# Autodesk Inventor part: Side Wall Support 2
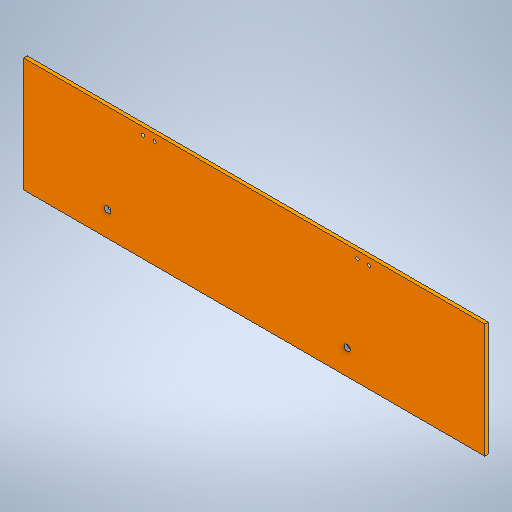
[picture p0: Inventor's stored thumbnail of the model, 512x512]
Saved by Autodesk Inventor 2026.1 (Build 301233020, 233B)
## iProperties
Created: 2026-11
Part Number: Side Wall Support 2
Material: Generic
Document SubType Name: Modeling
Designer: hp
Density: 1 g/cm^3
Appearance: Default
Author: hp
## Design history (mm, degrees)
sketch "Sketch1"
  geometry: L1 (0, 0)-(645, 0); L2 (645, 0)-(645, 160); L3 (645, 160)-(0, 160); L4 (0, 160)-(0, 0)
  constraints: 8 end point, 2 parallel, 1 horizontal, 1 perpendicular
  dimensions: "d0" = 645 distance of L3.end L2.end; "d1" = 160 distance of L2.end L1.end
extrude "Extrusion1" new body sketch "Sketch1" distance "d2" = 5; taper "d3" = 0 deg
sketch "Sketch2"
  geometry: 4 further points
hole "Hole1" sketch "Sketch2" at (-483, 150), (-467, 150), (-183, 150), (-167, 150) diameter "d4" = 4.5; stored, may be unused: countersink angle "d8" = 90 deg, drill point angle "d10" = 0 deg; dims "d5" = 6, "d6" = 4, "d7" = 2, "d9" = 8
sketch "Sketch3"
  geometry: 2 further points
hole "Hole2" sketch "Sketch3" at (-452.5, 35), (-117.5, 35) diameter "d11" = 9; stored, may be unused: countersink angle "d15" = 90 deg, drill point angle "d17" = 0 deg; dims "d12" = 6, "d13" = 4, "d14" = 2, "d16" = 8
body "Solid1"
